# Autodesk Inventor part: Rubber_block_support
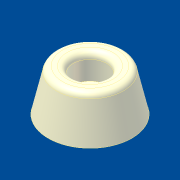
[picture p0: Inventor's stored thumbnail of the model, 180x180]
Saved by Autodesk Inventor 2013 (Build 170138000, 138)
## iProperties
Shininess: 31.0
Length Units: 11269
Angle Units: 11279
Time Units: 11290
Mass Units: 11283
Length Display Precision: 3
Angle Display Precision: 2
Created: 2001-04
Part Number: Rubber_block_support
Material: Standard
Document SubType Name: Modellieren
Designer: dl
Density: 1 g/cm^3
Density: 0.0
Volumn: 0.0
Area: 0.0
PropertySet Name: Model Information
Control State: 0
Master: False
Checked Out: False
Author: dl
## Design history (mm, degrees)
body "Solid1"
sketch "Sketch2"
  geometry: C1 r 7.75 at (0, 0) reference; 1 further point
  constraints: 1 coincident
revolve "Revolution1" stored, may be unused: angle "d3" = 90 deg
hole "Hole1" sketch "Sketch2" diameter "d4" = 5.5; stored, may be unused: countersink angle "d8" = 60 deg, drill point angle "d10" = 118 deg; dims "d5" = 6, "d6" = 8, "d7" = 6, "d9" = 8
fillet "Fillet1" dims "d11" = 1.5
sketch "Sketch1"
  geometry: L1 (-0.059, 1.707)-(-0.059, 11.707); L2 (-0.059, 11.707)-(7.691, 11.707); L3 (7.691, 11.707)-(9.941, 1.707); L4 (9.941, 1.707)-(-0.059, 1.707)
  constraints: 8 end point, 1 horizontal, 1 perpendicular, 1 vertical
  dimensions: "d0" = 10 distance of L1.start L1.end; "d1" = 10 distance of L3.end L1.start; "d2" = 7.75 distance of L1.end L2.end
